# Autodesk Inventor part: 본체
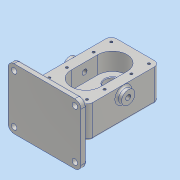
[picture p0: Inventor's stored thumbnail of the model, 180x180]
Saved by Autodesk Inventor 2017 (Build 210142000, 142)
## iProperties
Part Number: 본체
Material: 알루미늄 6061
Document SubType Name: Modeling
Designer: MRC
Density: 2.7 g/cm^3
Appearance: 알루미늄 - 평지
Mass: 1472.54 g
Surface Area: 818.394 cm^2
Volume: 545.387 cm^3
Author: MRC
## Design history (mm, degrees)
sketch "스케치1"
  geometry: L1 (40, -60)-(-40, -60); L2 (-40, -60)-(-40, 60); L3 (-40, 60)-(40, 60); L4 (40, 60)-(40, -60); L5 (40, -60)-(-40, 60); L6 (-40, -60)-(40, 60); 1 further point
  constraints: 12 end point, 2 midpoint, 2 parallel, 1 horizontal, 1 perpendicular
  dimensions: "d0" = 80 distance of L2.end L3.end; "d1" = 120 distance of L3.end L1.start
extrude "돌출1" new body sketch "스케치1" distance "d2" = 14; taper "d4" = 0 deg; dims "d3" = 39, "d5" = 0
fillet "모깎기1" dims "d6" = 9
sketch "스케치2"
  geometry: L1 (0, 22)-(0, -22); L2 (-24, 22)-(-24, -22); L3 (24, -22)-(24, 22); L4 (-31, 22)-(31, 22); A1 r 9 centre (-31, 51) between (-31, 60) and (-40, 51) reference; A2 r 24 centre (0, 22) between (24, 22) and (-24, 22); A3 r 24 centre (0, -22) between (-24, -22) and (24, -22); 2 further points
  constraints: 10 end point, 4 point on circle, 4 tangent, 2 centre point, 2 midpoint, 1 coincident, 1 horizontal, 1 parallel, 1 vertical
  dimensions: "d8" = 48 distance between parallel lines of L2 L3; "d10" = 29 distance from line of L4 A1.centre; "d11" = 44 distance of L1.end L1.start
extrude "돌출2" cut sketch "스케치2" distance "d12" = 29; taper "d13" = 0 deg
sketch "스케치3"
  geometry: C1 r 12.5 at (0, 22); A1 r 24 centre (0, 22) between (24, 22) and (-24, 22) reference; 1 further point
  constraints: 1 centre point, 1 coincident
  dimensions: "d14" = 25 diameter of C1
extrude "돌출3" cut sketch "스케치3" distance "d15" = 15; taper "d16" = 0 deg
sketch "스케치4"
  geometry: C1 r 12.5 at (0, 22) reference; C2 r 19 at (0, 22); 1 further point
  constraints: 1 centre point, 1 coincident
  dimensions: "d17" = 38 diameter of C2
extrude "돌출4" join sketch "스케치4" distance "d18" = 17; taper "d19" = 0 deg
sketch "스케치5"
  geometry: C1 r 12.5 at (0, 0) reference; C2 r 8.5 at (0, 0); 1 further point
  constraints: 1 centre point, 1 coincident
  dimensions: "d20" = 17 diameter of C2
extrude "돌출5" cut sketch "스케치5" stored distance "d21" = 17; taper "d22" = 0 deg
node "작업 평면1"
sketch "스케치6"
  geometry: C1 r 8.5 at (0, 0) reference; C2 r 14 at (0, 0); 1 further point
  constraints: 1 centre point, 1 coincident
  dimensions: "d24" = 28 diameter of C2
extrude "돌출6" cut sketch "스케치6" distance "d25" = 0.7; taper "d26" = 30 deg
sketch "스케치7"
  geometry: C1 r 14 at (0, 0) reference; C2 r 14 at (0, 0); 1 further point
  constraints: 1 centre point, 1 coincident
  dimensions: "d27" = 28 diameter of C2
extrude "돌출7" cut sketch "스케치7" distance "d28" = 6.6; taper "d29" = 0 deg
fillet "모깎기2" dims "d30" = 0.5
sketch "스케치8"
  geometry: C1 r 12.5 at (0, -22); A1 r 24 centre (0, -22) between (-24, -22) and (24, -22) reference; 1 further point
  constraints: 1 centre point, 1 coincident
  dimensions: "d31" = 25 diameter of C1
extrude "돌출8" cut sketch "스케치8" distance "d32" = 15; taper "d33" = 0 deg
chamfer "모따기1" distance "d34" = 1; stored, may be unused: second distance "d35" = 2, angle "d36" = 45 deg
sketch "스케치9"
  geometry: C1 r 11 at (-39, 51); 1 further point
  constraints: 1 centre point, 1 coincident
  dimensions: "d37" = 22 diameter of C1
extrude "돌출9" join sketch "스케치9" distance "d38" = 8; taper "d39" = 0 deg
hole "구멍1" diameter "d42" = 8.376; stored, may be unused: countersink angle "d46" = 90 deg, drill point angle "d48" = 118 deg; dims "d40" = 10, "d41" = 10, "d43" = 30, "d44" = 4, "d45" = 2, "d47" = 40
node "작업 평면2"
sketch "스케치10"
  geometry: L1 (-29, 17)-(91, 17); L2 (91, 17)-(91, -83); L3 (91, -83)-(-29, -83); L4 (-29, -83)-(-29, 17); L5 (50, 17)-(12, 17) reference; L6 (62, 0)-(62, -53) reference; L7 (0, 0)-(62, 0) reference; L8 (0, -53)-(0, 0) reference; L9 (62, -53)-(0, -53) reference; 3 further points
  constraints: 8 end point, 2 midpoint, 2 parallel, 1 coincident, 1 collinear, 1 horizontal, 1 perpendicular
  dimensions: "d50" = 120 distance of L1.start L1.end; "d51" = 100 distance of L3.end L1.start
extrude "돌출10" join sketch "스케치10" distance "d52" = 10; taper "d53" = 0 deg
fillet "모깎기3" dims "d54" = 10
sketch "스케치12"
  geometry: L1 (-80, 14)-(-60, 2.453); L2 (-80, -39)-(-60, -27.453); L3 (-80, 14)-(-80, -39); L4 (-60, -39)-(-60, 14) reference; L5 (-80, -46)-(-80, 34) reference; 1 further point
  constraints: 6 end point, 2 point on line, 1 collinear, 1 horizontal alignment, 1 vertical
  dimensions: "d57" = 53 distance of L1.start L2.start; "d58" = 60 deg angle of L3 L1; "d59" = 60 deg angle of L3 L2
extrude "돌출11" join sketch "스케치12" stored distance "d60" = 48; taper "d61" = 0 deg
sketch "스케치13"
  geometry: A1 r 9 centre (-31, -51) between (-40, -51) and (-31, -60) reference; A2 r 9 centre (31, -51) between (31, -60) and (40, -51) reference; A3 r 9 centre (31, 51) between (40, 51) and (31, 60) reference; A4 r 9 centre (-31, 51) between (-31, 60) and (-40, 51) reference; 9 further points
  constraints: 4 coincident
hole "구멍2" sketch "스케치13" at (-31, 51), (-31, -51), (31, -51), (31, 51), (31, 22), (31, -22), (-31, 22), (-31, -22) diameter "d62" = 4.134; stored, may be unused: countersink angle "d66" = 90 deg, drill point angle "d68" = 118 deg; dims "d63" = 10, "d64" = 4, "d65" = 2, "d67" = 12
sketch "스케치14"
  geometry: A1 r 10 centre (81, -73) between (81, -83) and (91, -73) reference; A2 r 10 centre (81, 7) between (91, 7) and (81, 17) reference; A3 r 10 centre (-19, 7) between (-19, 17) and (-29, 7) reference; A4 r 10 centre (-19, -73) between (-29, -73) and (-19, -83) reference; 5 further points
  constraints: 4 coincident
hole "구멍3" sketch "스케치14" at (-19, 7), (-19, -73), (81, -73), (81, 7) diameter "d69" = 9; stored, may be unused: countersink angle "d73" = 90 deg, drill point angle "d75" = 118 deg; dims "d70" = 10, "d71" = 4, "d72" = 2, "d74" = 12
fillet "모깎기4" dims "d76" = 3
fillet "모깎기5" dims "d77" = 3
sketch "스케치15"
  geometry: L1 (-29, 7)-(-29, -73) reference; L2 (-19, -83)-(81, -83) reference; 2 further points
  constraints: 1 other
  dimensions: "d78" = 60 distance from line of L1 point (31, -73); "d79" = 10 distance from line of L2 point (31, -73)
feature "엠보싱1" sketch "스케치15" dims "d0" = 80, "d1" = 120, "d8" = 48, "d10" = 29, "d11" = 44, "d80" = 0.5, "d81" = 0
node "솔리드1"
mirror "미러1"
node "투영된 루프1"
other parameters: "d23" = -0.7
